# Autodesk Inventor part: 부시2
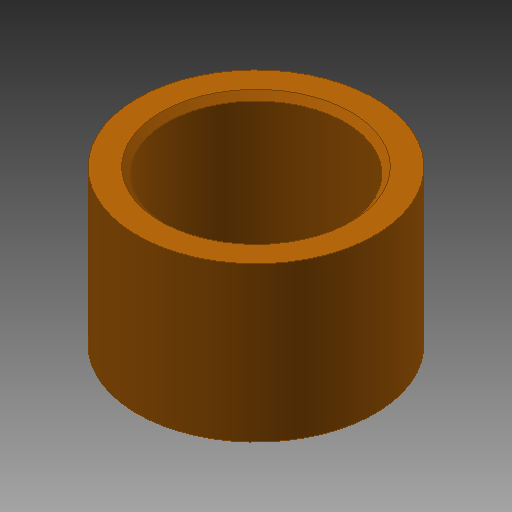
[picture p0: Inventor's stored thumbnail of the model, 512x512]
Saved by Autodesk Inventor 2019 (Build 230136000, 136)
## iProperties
Created: 2016-08
Part Number: 부시2
Material: 강철, 탄소
Document SubType Name: Modeling
Designer: mduedu
Density: 7.87 g/cm^3
Appearance: 주황색
Author: mduedu
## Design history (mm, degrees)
sketch "스케치1"
  geometry: C1 r 7.5 at (0, 0); C2 r 10 at (0, 0); 1 further point
  constraints: 2 centre point, 2 coincident
  dimensions: "d0" = 15 diameter of C1; "d1" = 20 diameter of C2
extrude "돌출1" new body sketch "스케치1" stored distance "d2" = 13; taper "d3" = 0 deg
chamfer "모따기1" distance "d4" = 0.5; stored, may be unused: second distance "d5" = 2, angle "d6" = 45 deg
node "솔리드1"
